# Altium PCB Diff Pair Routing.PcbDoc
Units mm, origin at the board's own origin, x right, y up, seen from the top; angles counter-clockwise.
Board outline 63.5 x 50.8 mm, 4 copper layers (Top Layer, Internal Plane 1, Mid-Layer 2, Bottom Layer), stack 1.57 mm thick; 9 components, 11 nets, 56 pads, 6 vias.
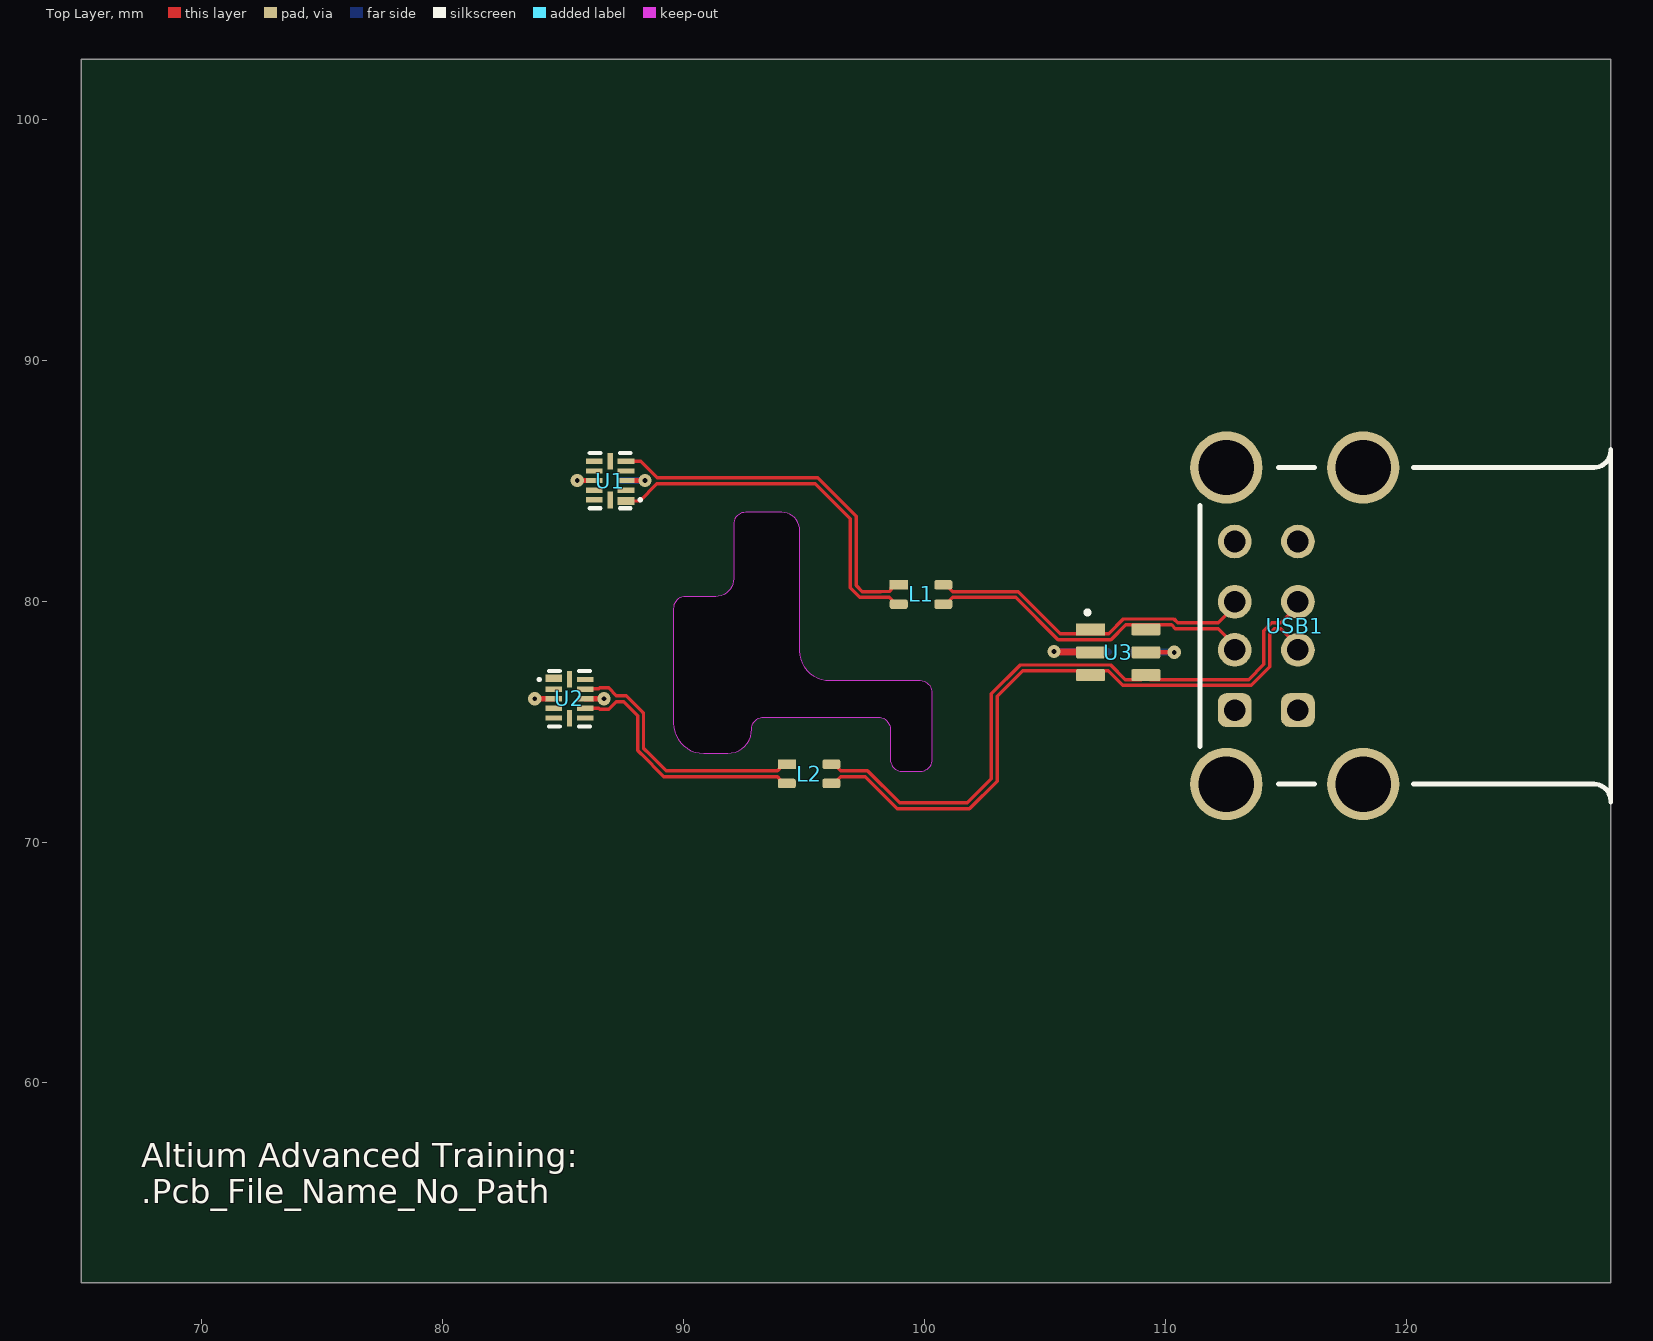
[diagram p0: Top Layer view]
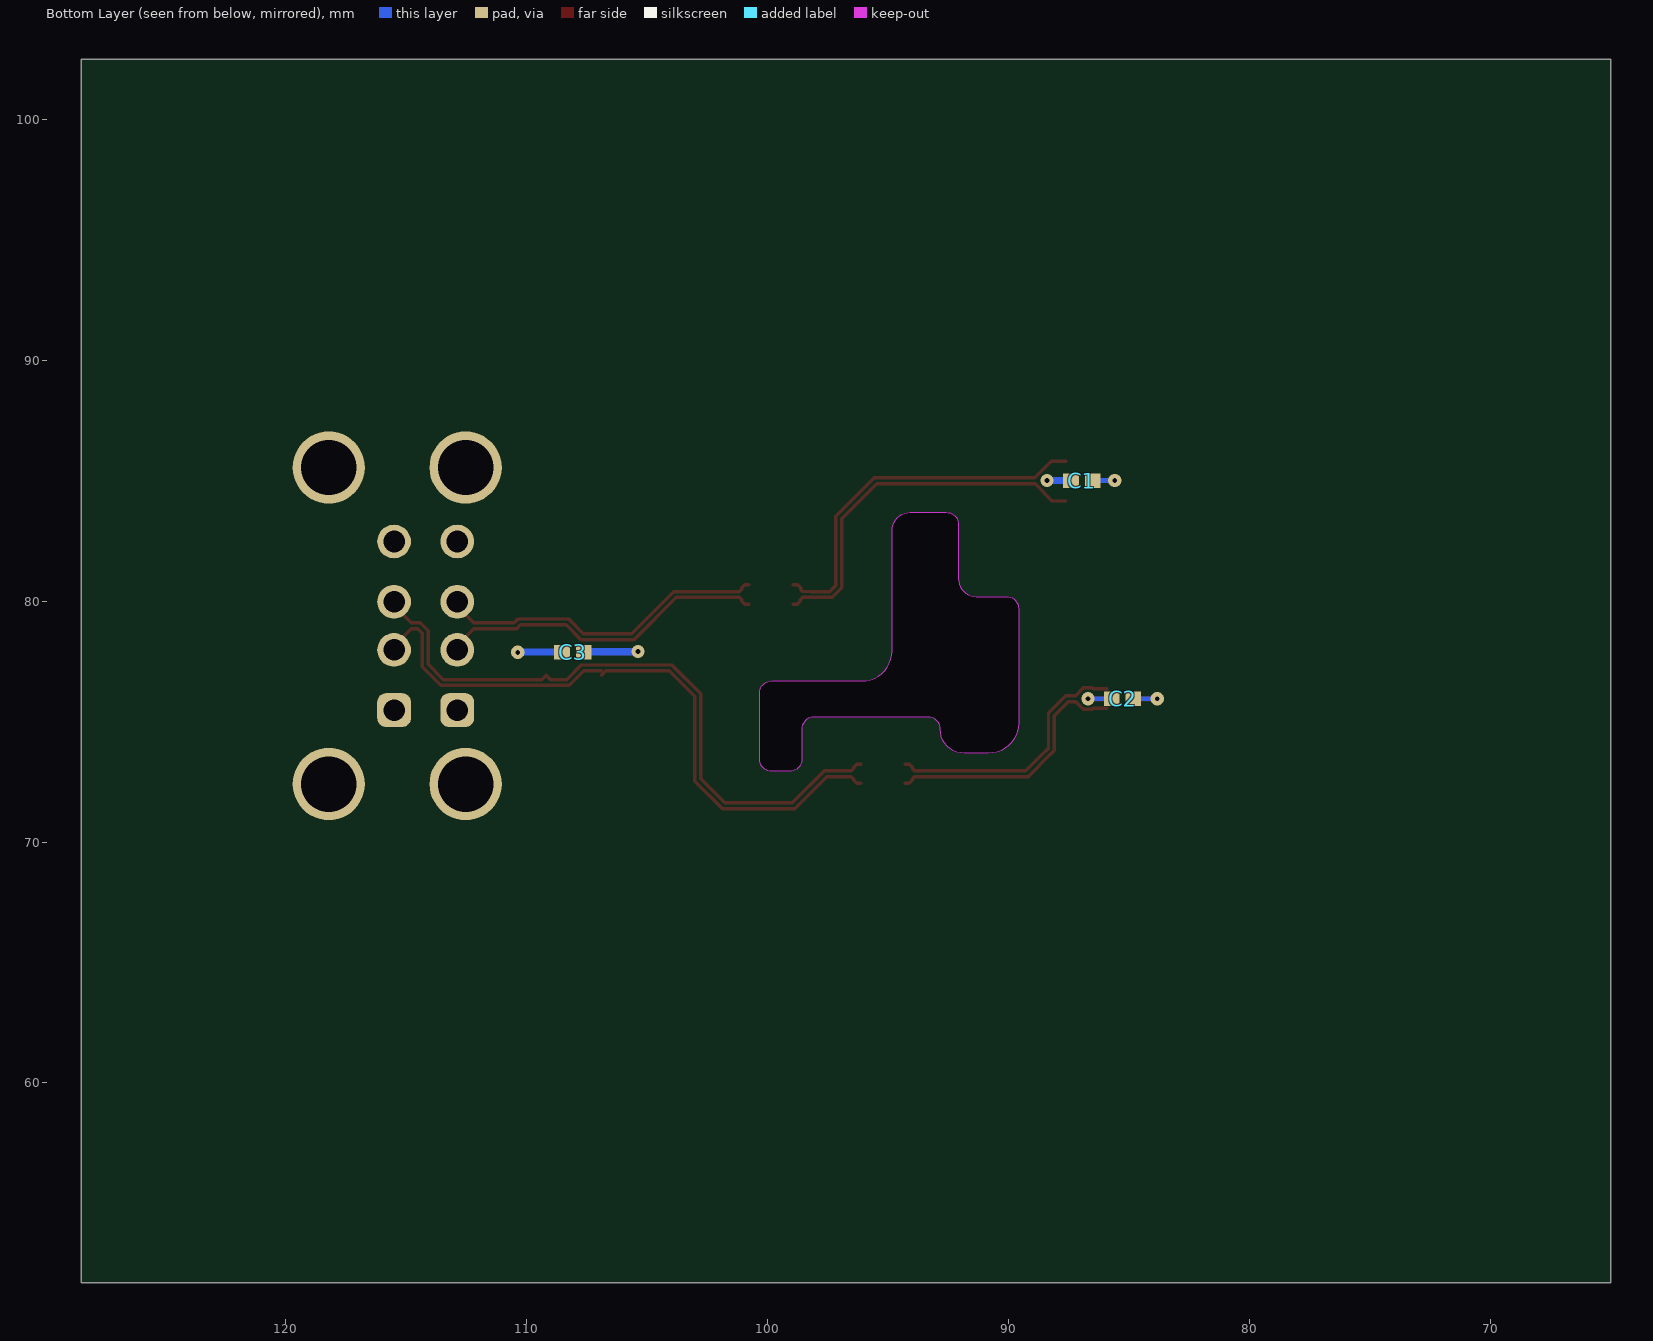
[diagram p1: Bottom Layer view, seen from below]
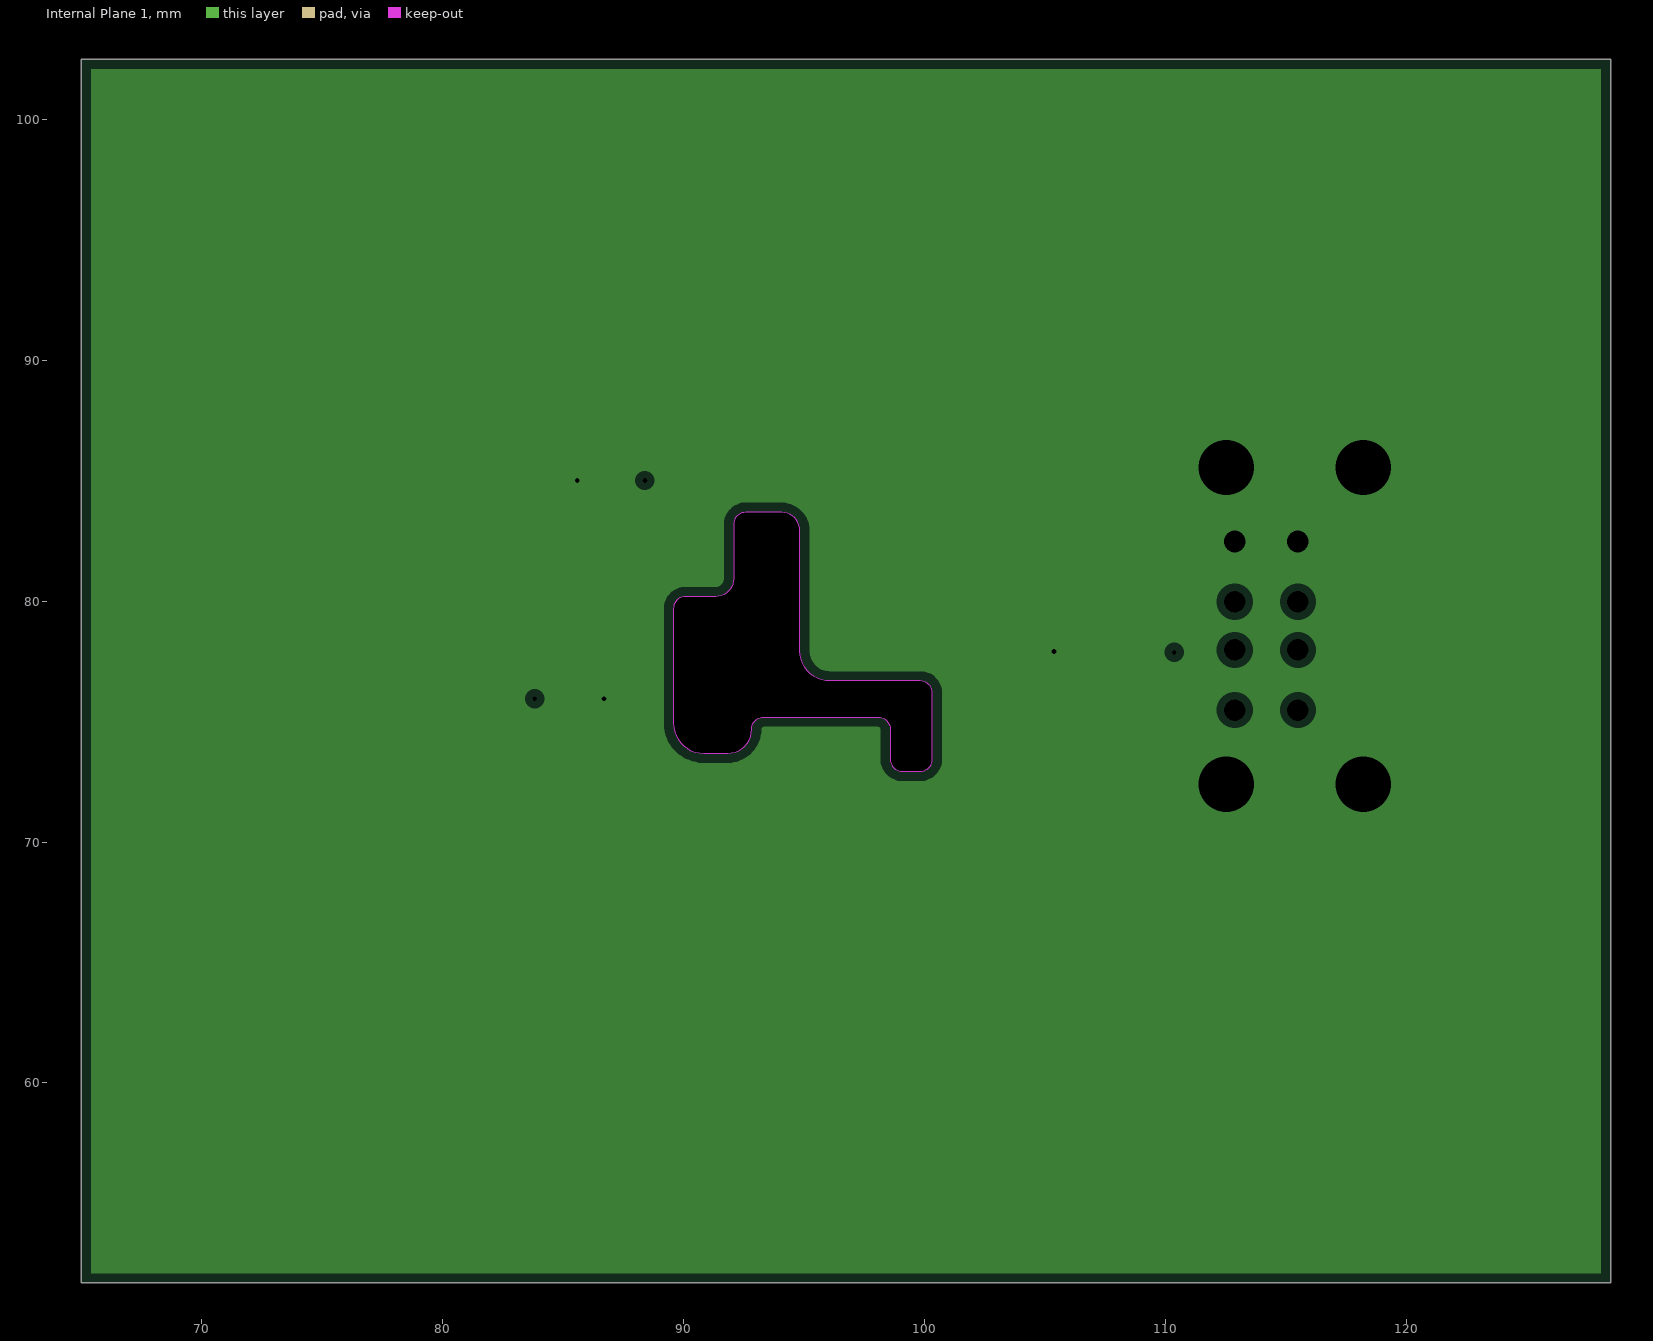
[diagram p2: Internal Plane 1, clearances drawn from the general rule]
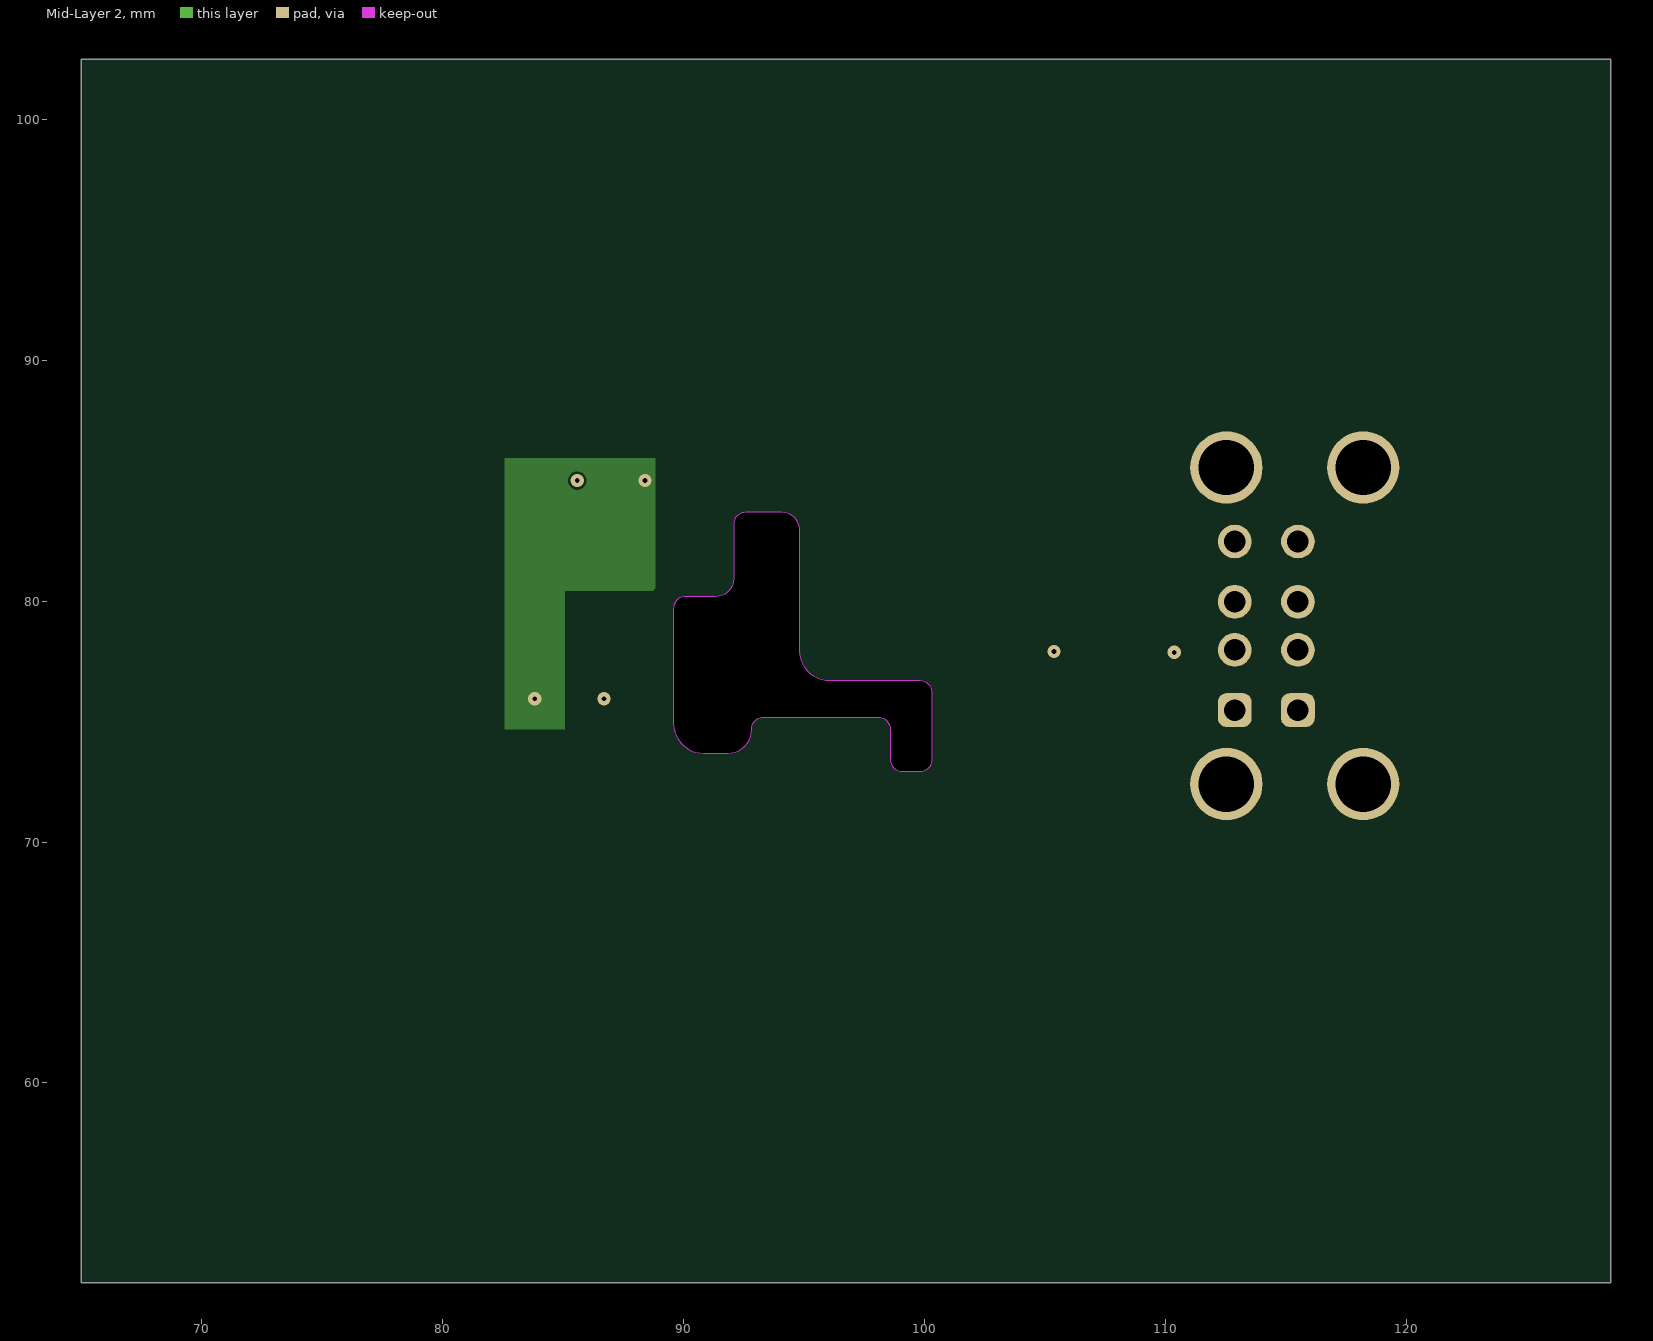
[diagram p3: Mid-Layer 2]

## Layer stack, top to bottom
Top Solder: solder mask 0.02, Solder Resist, Dk 2.5
Top Layer: signal copper 0.044
Dielectric  1: core 0.108, FR-4 (1 x 2116), Dk 3.6
Internal Plane 1: plane copper 0.033, net GND
Dielectric 2: prepreg 1.2, FR-4, Dk 4.2
Mid-Layer 2: signal copper 0.033
Dielectric  3: core 0.108, FR-4 (1 x 2116), Dk 3.6
Bottom Layer: signal copper 0.044
Bottom Solder: solder mask 0.02, Solder Resist, Dk 2.5

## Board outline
65,51.7 128.5,51.7 128.5,102.5 65,102.5
cut-out: 92.585,83.687 ccw(c92.585,83.187) 92.085,83.187 92.085,80.937 cw(c91.335,80.937) 91.335,80.187 90.085,80.187 ccw(c90.085,79.687) 89.585,79.687 89.585,74.937 ccw(c90.835,74.937) 90.835,73.687 91.835,73.687 ccw(c91.835,74.687) 92.835,74.687 cw(c93.335,74.687) 93.335,75.187 98.085,75.187 cw(c98.085,74.687) 98.585,74.687 98.585,73.437 ccw(c99.085,73.437) 99.085,72.937 99.835,72.937 ccw(c99.835,73.437) 100.335,73.437 100.335,76.187 ccw(c99.835,76.187) 99.835,76.687 96.085,76.687 cw(c96.085,77.937) 94.835,77.937 94.835,82.937 ccw(c94.085,82.937) 94.085,83.687

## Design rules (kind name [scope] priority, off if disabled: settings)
Clearance Clearance_DDR_GND_Polygons [IsRegion AND InNet ('GND') vs (IsRegion Or IsTrack or IsArc or IsVia) AND (InNetClass('DDR_ALL'))] p1: gap=0.508 ignorepadtopadclearanceinfootprint=FALSE except(0: Arc-Hole Track-Hole SMDPad-Hole THPad-Hole Via-Hole Fill-Hole Poly-Hole Region-Hole Text-Hole)
Clearance "Clearance_DiffPair Separation_GND planes" [(InDifferentialPairClass('All Differential Pairs')) and (not IsVia) vs IsRegion AND InNET('GND')] p2: gap=0.508 ignorepadtopadclearanceinfootprint=FALSE except(0: Arc-Hole Track-Hole SMDPad-Hole THPad-Hole Via-Hole Fill-Hole Poly-Hole Region-Hole Text-Hole)
Clearance Clearance_Keep_Out [OnLayer('Keep-Out Layer')] p3: gap=0.5 ignorepadtopadclearanceinfootprint=FALSE except(0: Arc-Hole Track-Hole SMDPad-Hole THPad-Hole Via-Hole Fill-Hole Poly-Hole Region-Hole Text-Hole)
Clearance Clearance_Fiducials [HasFootprint('FIDUCIAL_0.8MM')] p4: gap=0.4 ignorepadtopadclearanceinfootprint=FALSE except(0: Arc-Hole Track-Hole SMDPad-Hole THPad-Hole Via-Hole Fill-Hole Poly-Hole Region-Hole Text-Hole)
Clearance "Clearance_DiffPair Separation" [(InDifferentialPairClass('All Differential Pairs'))] p5: gap=0.38 ignorepadtopadclearanceinfootprint=FALSE except(0: Arc-Hole Track-Hole SMDPad-Hole THPad-Hole Via-Hole Fill-Hole Poly-Hole Region-Hole Text-Hole)
Clearance Clearance_NPTH [(ObjectKind = 'Pad') And (Layer = 'MultiLayer') And (Net = 'No Net') And (PadIsPlated = 'False')] p6: gap=0.3 ignorepadtopadclearanceinfootprint=FALSE except(0: Arc-Hole Track-Hole SMDPad-Hole THPad-Hole Via-Hole Fill-Hole Poly-Hole Region-Hole Text-Hole) // This is all the NPTH
Clearance Clearance_Polys [IsRegion vs IsRegion Or IsTrack or IsArc or IsPad or IsFill] p7: gap=0.2 ignorepadtopadclearanceinfootprint=FALSE except(0: Arc-Hole Track-Hole SMDPad-Hole THPad-Hole Via-Hole Fill-Hole Poly-Hole Region-Hole Text-Hole)
Clearance Clearance_Pads_DPs [(InDifferentialPairClass('All Differential Pairs')) vs (IsPad AND HasFootprint('UQFN12')) or (IsPad AND HasFootprint('ACM2012')) or (IsPad AND HasFootprint('DISPLAYPORT_SOCKET_MOLEX')) or (IsPad AND HasFootprint('QFN50P300X300X50-16N'))or (IsPad AND HasFootprint('CC0402')) or (IsPad AND HasFootprint('RC0402')) or (IsPad AND HasFootprint('SSOP28')) or (IsPad AND HasFootprint('SOT23-6L')) or (IsPad AND HasFootprint('SOCKET-BGA400-SG-BGA-6052'))] p8: gap=0.1 ignorepadtopadclearanceinfootprint=FALSE except(0: Arc-Hole Track-Hole SMDPad-Hole THPad-Hole Via-Hole Fill-Hole Poly-Hole Region-Hole Text-Hole)
Clearance Clearance_1 [All] p9: gap=0.1 ignorepadtopadclearanceinfootprint=FALSE except(0: Arc-Hole Track-Hole SMDPad-Hole THPad-Hole Via-Hole Fill-Hole Poly-Hole Region-Hole Text-Hole)
Clearance "Clearance same net" [All vs IsVia Or IsPad] p10 off: gap=0.1 ignorepadtopadclearanceinfootprint=FALSE except(0: Arc-Hole Track-Hole SMDPad-Hole THPad-Hole Via-Hole Fill-Hole Poly-Hole Region-Hole Text-Hole)
ComponentClearance ComponentClearance_TP [HasFootprint('TESTPAD_1270um') vs HasFootprint('TESTPAD_1270um')] p1: gap=0.64 collisioncheckmode=3 verticalgap=4 showdistances=FALSE // Based on 1.91mm between centres on the RA2R coda systems receptacle and test probes (PA2 series)
ComponentClearance ComponentClearance_RJ45 [(ObjectKind = 'Component') And (Footprint = 'RJ45_TRJG16368CNL') vs (ObjectKind = 'Component') And (Footprint = 'SFP_CAGE_SINGLE_Rev2')] p2: gap=0 collisioncheckmode=3 verticalgap=0 showdistances=FALSE
ComponentClearance [All] p3: gap=0.2 collisioncheckmode=3 verticalgap=0.2 showdistances=FALSE
DiffPairsRouting DiffPairsRouting_90R_DIFF [InDifferentialPairClass('90R_DIFF')] p1: maxlimit=0.102 minlimit=0.102 mostfreqgap=0.102 toplayer_minwidth=0.142 toplayer_maxwidth=0.142 toplayer_prefwidth=0.142 midlayer2_minwidth=0.079 midlayer2_maxwidth=0.079 midlayer2_prefwidth=0.079 bottomlayer_minwidth=0.142 bottomlayer_maxwidth=0.142 bottomlayer_prefwidth=0.142 impedanceprofiledriven=TRUE impedanceprofileid={F718B7EE-F449-431B-8CDC-434D7816C5EC} impedanceprofilevalue=90.000000 maxuncoupledlength=15
HoleSize [All] p1: absolutevalues=TRUE maxlimit=3.2 minlimit=0.15 maxpercent=80.000 minpercent=20.000
HoleToHoleClearance HoleToHoleVia0.45mm [(ObjectKind = 'Via') AND (AsMM(ViaDiameter) = 0.45) AND (AsMM(HoleDiameter) = 0.2)] p1: gap=0.35 allowstackedmicrovias=FALSE
HoleToHoleClearance "HoleToHoleVia 0.55mm" [(ObjectKind = 'Via') AND (AsMM(ViaDiameter) = 0.55) AND (AsMM(HoleDiameter) = 0.25)] p2: gap=0.4 allowstackedmicrovias=FALSE
HoleToHoleClearance "HoleToHoleVia 0.406" [(ObjectKind = 'Via') AND (AsMM(ViaDiameter) = 0.406) AND (AsMM(HoleDiameter) = 0.20)] p3: gap=0.306 allowstackedmicrovias=FALSE
HoleToHoleClearance [All] p4: gap=0.254 allowstackedmicrovias=TRUE
MatchedLengths "Schematic Matched Net Lengths" [InDifferentialPairClass('90R_DIFF')] p1: tolerance=0.5 checknetsindiffpair=TRUE checkdiffpairvsdiffpair=FALSE checkxsignals=FALSE checkothers=FALSE
MinimumAnnularRing MinimumAnnularRing_1 [All] p1 off: minimumring=0.124
MinimumAnnularRing [All] p2 off: minimumring=0.175
MinimumSolderMaskSliver "MinimumSolderMaskSliver_Text to pads" [IsPad vs IsText] p1: minsoldermaskwidth=0.07
MinimumSolderMaskSliver MinimumSolderMaskSliver_Vias [All vs IsVIA] p2: minsoldermaskwidth=0.07
MinimumSolderMaskSliver [All] p3 off: minsoldermaskwidth=0.07
PlaneClearance PlaneClearance_1 [(ObjectKind = 'Pad') And (Layer = 'MultiLayer') And (Net = 'No Net') And (PadIsPlated = 'False')] p1: clearance=0.3
PlaneClearance [All] p2: clearance=0.3 // Email ChrisM for Wurth 07-07-2014 300um min (or 275 if not poss) - was 225 before
PlaneConnect "PlaneConnect on SFP age with islated copper" [(InComponent('CAGE1') AND ((ObjectKind = 'Pad') And (Rotation = '0.001')))] p1: planeconnectstyle=Direct reliefexpansion=0.508 reliefentries=4 reliefconductorwidth=0.254 reliefairgap=0.254
PlaneConnect PlaneConnect_VIAs [IsVia] p2: planeconnectstyle=Direct reliefexpansion=0.508 reliefentries=4 reliefconductorwidth=0.254 reliefairgap=0.254
PlaneConnect PlaneConnect_1 [All] p3: planeconnectstyle=Relief reliefexpansion=0.5 reliefentries=4 reliefconductorwidth=0.25 reliefairgap=0.25
PolygonConnect PolygonConnect_Vias [IsVia] p1: connectstyle=Direct reliefconductorwidth=0.254 reliefentries=4 polygonreliefangle="90 Angle" airgapwidth=0.254
PolygonConnect [(ObjectKind = 'Pad') And (Layer = 'MultiLayer')] p2: connectstyle=Relief reliefconductorwidth=0.254 reliefentries=4 polygonreliefangle="90 Angle" airgapwidth=0.254
PolygonConnect PolygonConnect_1 [All] p3: connectstyle=Direct reliefconductorwidth=0.254 reliefentries=4 polygonreliefangle="90 Angle" airgapwidth=0.254
RoutingVias [All] p1: holewidth=0.2 width=0.45 viastyle="Through Hole" minholewidth=0.2 minwidth=0.406 maxholewidth=0.5 maxwidth=0.8
SMDEntry [All] p1: side=TRUE corner=TRUE anyangle=FALSE
SilkToSilkClearance [All] p1 off: silktosilkclearance=0.1
SilkToSolderMaskClearance [IsPad] p1 off: minsilkscreentomaskgap=0.1 clearancetoexposedcopper=TRUE
SolderMaskExpansion "SolderMaskExpansion_IsVia 0.45mm" [(ObjectKind = 'Via') And (AsMM(ViaDiameter) = 0.45) And (AsMM(HoleDiameter) = 0.2)] p1: expansion=-0.125 istentingtop=FALSE // 0.45 pad size Vias with 0.2mm drill
SolderMaskExpansion "SolderMaskExpansion_IsVia 0.55mm" [(ObjectKind = 'Via') And (AsMM(ViaDiameter) = 0.55)  And (AsMM(HoleDiameter) = 0.25)] p2: expansion=-0.15 istentingtop=FALSE // 0.55 pad size Vias with 0.25mm drill
SolderMaskExpansion "SolderMaskExpansion_IsVia 0.55mm_0.2mmhole" [(ObjectKind = 'Via') And (AsMM(ViaDiameter) = 0.55)  And (AsMM(HoleDiameter) = 0.20)] p3: expansion=-0.175 istentingtop=FALSE // 0.55 pad size Vias with 0.25mm drill
SolderMaskExpansion SolderMaskExpansion_IsVia_0.406mm [(ObjectKind = 'Via') And (AsMM(ViaDiameter) = 0.406) And (AsMM(HoleDiameter) = 0.2)] p4: expansion=-0.103 istentingtop=FALSE // 0.45 pad size Vias with 0.2mm drill
SolderMaskExpansion [All] p5: expansion=0 istentingtop=FALSE // Need to set to 0 on Gerber generation (else 0.7mm is wurths rule)
SolderMaskExpansion SolderMaskExpansion_1 [All] p6: expansion=0.07 istentingtop=FALSE // Need to set to 0 on Gerber generation (else 0.7mm is wurths rule)
Width [All] p1: maxlimit=3 minlimit=0.127 preferedwidth=0.2 minimp=0.000000 maximp=0.000000 favimp=0.000000
21 further rules are at their usual default settings.

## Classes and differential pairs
differential pair class 90R_DIFF: D1 D2 J_D1 J_D2
differential pair D1: +D1_P -D1_N
differential pair J_D2: +J_D2_P -J_D2_N
differential pair J_D1: +J_D1_P -J_D1_N
differential pair D2: +D2_P -D2_N

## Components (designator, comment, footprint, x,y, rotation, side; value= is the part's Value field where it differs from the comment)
C1 "100nF" CC0402 86.961,85.007 r0 bottom
C2 "100nF" CC0402 85.269,75.949 r180 bottom
C3 "100nF" CC0402 108.087,77.888 r180 bottom
L1 "90R@100MHz" ACM2012 99.865,80.278 r0 top
L2 "90R@100MHz" ACM2012 95.218,72.835 r0 top
U1 "NCN1154" UQFN12 86.961,85.007 r90 top
U2 "NCN1154" UQFN12 85.269,75.949 r270 top
U3 "DVIULC6-4SC6" SOT23-6L 106.9,78.828 r270 top
USB1 "DUAL USB" USB-A_RA_DUAL 128.5,78.978 r90 top

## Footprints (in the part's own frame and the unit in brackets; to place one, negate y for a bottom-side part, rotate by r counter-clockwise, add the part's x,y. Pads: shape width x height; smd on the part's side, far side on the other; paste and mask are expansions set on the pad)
ACM2012 [mm] "Common Mode Choke 0805 package"
  rect 0.75x0.4 smd: 1(-0.925,0.4)
  rrect50% 0.75x0.4 smd: 2(-0.925,-0.4) 3(0.925,-0.4) 4(0.925,0.4)
  body extent -1.1,-0.7 1.1,0.7, height 1.3
CC0402 [mm] "Standard 0402 Capacitor 0.5mm thick"
  rect 0.65x0.6 smd: 1(-0.45,0) 2(0.45,0)
  body extent -0.53,-0.28 0.53,0.28, height 0.51
SOT23-6L [mm]
  rect 0.5x1.2 smd: 1(0,0)
  rrect25% 0.5x1.2 smd: 2(0.95,0) 3(1.9,0) 4(1.9,2.3) 5(0.95,2.3) 6(0,2.3)
  silkscreen extent -0.78,-0.2 -0.63,-0.05, body extent -0.58,-0.35 2.48,2.65, height 1.46
UQFN12 [mm] "UQFN12 1.7x2.0, 0.4P - CASE 523AE-01"
  rect 0.32x0.69 smd: 1(-0.85,-0.655)
  rect 0.22x0.69 smd: 2(-0.4,-0.655) 3(0,-0.655) 4(0.4,-0.655) 5(0.8,-0.655) 7(0.8,0.655) 8(0.4,0.655) 9(0,0.655) 10(-0.4,0.655) 11(-0.8,0.655)
  rect 0.69x0.22 smd: 6(0.805,0) 12(-0.805,0)
  silkscreen extent -1.15,-1.26 1.15,0.85, body extent -1,-0.85 1,0.85, height 0.56
USB-A_RA_DUAL [mm] "Dual Stacked USB Type A Connector"
  rrect50% 1.4x1.4 hole 0.9: 1B(-3.5,12.99) 1T(-3.5,15.61)
  round 1.4 hole 0.9: 2B(-1,12.99) 2T(-1,15.61) 3B(1,12.99) 3T(1,15.61) 4B(3.5,12.99) 4T(3.5,15.61)
  round 3 hole 2.3: 5B(-6.57,10.28) 5B(6.57,10.28) 5T(-6.57,15.96) 5T(6.57,15.96)
  silkscreen extent -7.32,0 7.32,17.05, body extent -7.38,0 7.38,17, height 2.05

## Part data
C1 C2 C3: library part CAP_100nF, "Cap, 100nF, X7R, 16V, ±10%, CC0402"
L1 L2: library part FILTER, "CMNCK, 90R@100MHz, 50V, 400mA, ACM2012"
U1 U2: library part USB_UART, "3:1 High-Speed USB /UART/Auido Mux"
U3: library part ESD_Protector, "4-chl Ultra-Low Capacitance ESD protector with TVS diode"
USB1: library part USB, "RoHS compliant or Toby - KUSB-AS2N-WHT or Toby - KUSB-AS2N-BLK or 2EUK - UBAR-08S or 2EUK (Oupiin) - 8968-A08CRW"

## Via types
v1: diameter 0.55, hole 0.2, Top Layer to Bottom Layer, 6 vias

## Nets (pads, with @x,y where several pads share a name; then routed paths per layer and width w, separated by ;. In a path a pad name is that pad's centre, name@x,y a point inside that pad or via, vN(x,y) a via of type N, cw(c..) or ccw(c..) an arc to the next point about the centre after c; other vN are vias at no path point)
3v3_SB: C1.2 C2.2 U1.3 U2.3 | length 3.6
  Top Layer w0.2: U1.3 87.617,85.009 88.4,85.009 v1(88.401,85.01)
  Top Layer w0.22: v1@83.831,75.949 U2.3
  Top Layer w0.3: v1(83.828,75.947) v1@83.831,75.949
  Bottom Layer w0.2: v1(83.828,75.947) 84.816,75.947 C2.2
  Bottom Layer w0.3: C1.2 v1@88.401,85.007
5v0_USB: C3.1 U3.5 | length 3
  Top Layer w0.2: U3.5 109.201,77.877 v1(110.379,77.876) v1(110.379,77.876)
  Bottom Layer w0.3: C3.1 v1@110.379,77.888
D1_N: L1.2 U1.1 | length 15.4
  Top Layer w0.142: U1.1 88.179,84.157 88.898,84.876 95.473,84.876 96.925,83.425 96.925,80.55 97.319,80.156 98.288,80.156 ; 98.289,80.156 98.552,80.156 98.654,80.055 98.654,80.005 98.78,79.878 L1.2
D1_P: L1.1 U1.5 | length 15.4
  Top Layer w0.142: U1.5 88.235,85.807 88.921,85.12 95.575,85.12 97.169,83.526 97.169,80.651 97.42,80.4 98.187,80.4 98.552,80.4 98.636,80.484 98.636,80.549 98.765,80.678 L1.1
D2_N: L2.2 U2.8 | length 10.8
  Top Layer w0.142: U2.8 85.925,75.548 86.482,75.548 86.524,75.506 86.894,75.506 87.219,75.831 87.519,75.831 88.1,75.25 88.1,73.8 88.45,73.45 88.975,72.925 89.187,72.713 93.905,72.713 94.007,72.612 94.007,72.562 94.133,72.435 L2.2
D2_P: L2.1 U2.10 | length 10.8
  Top Layer w0.142: U2.10 85.93,76.356 86.482,76.356 86.524,76.398 86.894,76.398 87.217,76.075 87.62,76.075 88.273,75.423 88.344,75.351 88.344,73.901 88.623,73.623 88.855,73.39 89.076,73.169 89.288,72.957 93.905,72.957 93.989,73.04 93.989,73.106 94.118,73.235 L2.1
GND: C1.1 C2.1 C3.2 U1.9 U2.9 U3.2 USB1.4B USB1.4T USB1.5B USB1.5T | length 8
  Top Layer w0.2: v1(85.591,85.005) 85.592,85.006 86.304,85.006 U1.9
  Top Layer w0.22: v1@85.523,85.007 U1.9 ; U2.9 v1@86.706,75.949
  Top Layer w0.3: v1@86.706,75.949 v1(86.709,75.952) ; v1(105.381,77.906) 105.394,77.892 106.886,77.892 U3.2
  Bottom Layer w0.2: v1(85.591,85.005) 86.508,85.005 C1.1 ; C2.1 85.721,75.952 v1(86.709,75.952)
  Bottom Layer w0.3: v1(105.381,77.906) 105.39,77.897 107.628,77.897 C3.2
J_D1_N: L1.3 U3.6 USB1.2T | length 13.8
  Top Layer w0.142: L1.3 100.949,79.878 101.076,80.005 101.076,80.055 101.177,80.156 103.801,80.156 105.55,78.407 107.752,78.407 108.361,79.016 110.264,79.016 110.424,78.856 112.092,78.856 112.21,78.856 112.89,78.176 USB1.2T
J_D1_P: L1.4 U3.1 USB1.3T | length 13.8
  Top Layer w0.142: L1.4 100.949,80.678 101.076,80.552 101.076,80.501 101.177,80.4 103.902,80.4 105.651,78.651 107.651,78.651 108.26,79.26 110.365,79.26 110.525,79.1 111.991,79.1 112.21,79.1 112.89,79.78 USB1.3T
J_D2_N: L2.3 U3.3 USB1.2B | length 27.1
  Top Layer w0.142: L2.3 96.302,72.435 96.429,72.562 96.429,72.612 96.53,72.713 97.542,72.713 98.874,71.381 101.876,71.381 103.025,72.53 103.025,76.05 104.081,77.106 106.722,77.106 U3.3 ; U3.3@106.9,77.105 107.639,77.105 108.243,76.501 113.571,76.501 114.344,77.274 114.344,78.675 114.525,78.856 114.8,78.856 115.51,78.146 USB1.2B
J_D2_P: L2.4 U3.4 USB1.3B | length 27.2
  Top Layer w0.142: L2.4 96.302,73.235 96.429,73.108 96.429,73.058 96.53,72.957 97.643,72.957 98.975,71.625 101.775,71.625 102.781,72.631 102.781,76.151 103.98,77.35 107.74,77.35 108.344,76.746 109.017,76.746 U3.4 109.382,76.746 113.47,76.746 114.1,77.375 114.1,78.776 114.424,79.1 114.8,79.1 115.51,79.81 USB1.3B
pads on no net: U1.2 U1.4 U1.6 U1.7 U1.8 U1.10 U1.11 U1.12 U2.1 U2.2 U2.4 U2.5 U2.6 U2.7 U2.11 U2.12 USB1.1B USB1.1T

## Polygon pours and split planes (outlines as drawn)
3v3_SB on Mid-Layer 2 "3V3_SB_L03_P000" (solid, pour order 0): 88.835,85.937 88.835,80.437 85.085,80.437 85.085,74.687 82.585,74.687 82.585,83.187 82.585,85.937
GND on Internal Plane 1 (split plane): 128.098,52.102 65.402,52.102 65.402,102.098 128.098,102.098

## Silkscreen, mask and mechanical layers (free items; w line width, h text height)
Top Overlay:
  text "Altium Advanced Training:  / .Pcb_File_Name_No_Path" at 67.5,55 h1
